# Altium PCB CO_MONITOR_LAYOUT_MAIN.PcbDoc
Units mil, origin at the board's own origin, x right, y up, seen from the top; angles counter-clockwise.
Board outline 2980 x 4230 mil, 2 copper layers (Top Layer, Bottom Layer); 116 components, 104 nets, 435 pads, 124 vias.
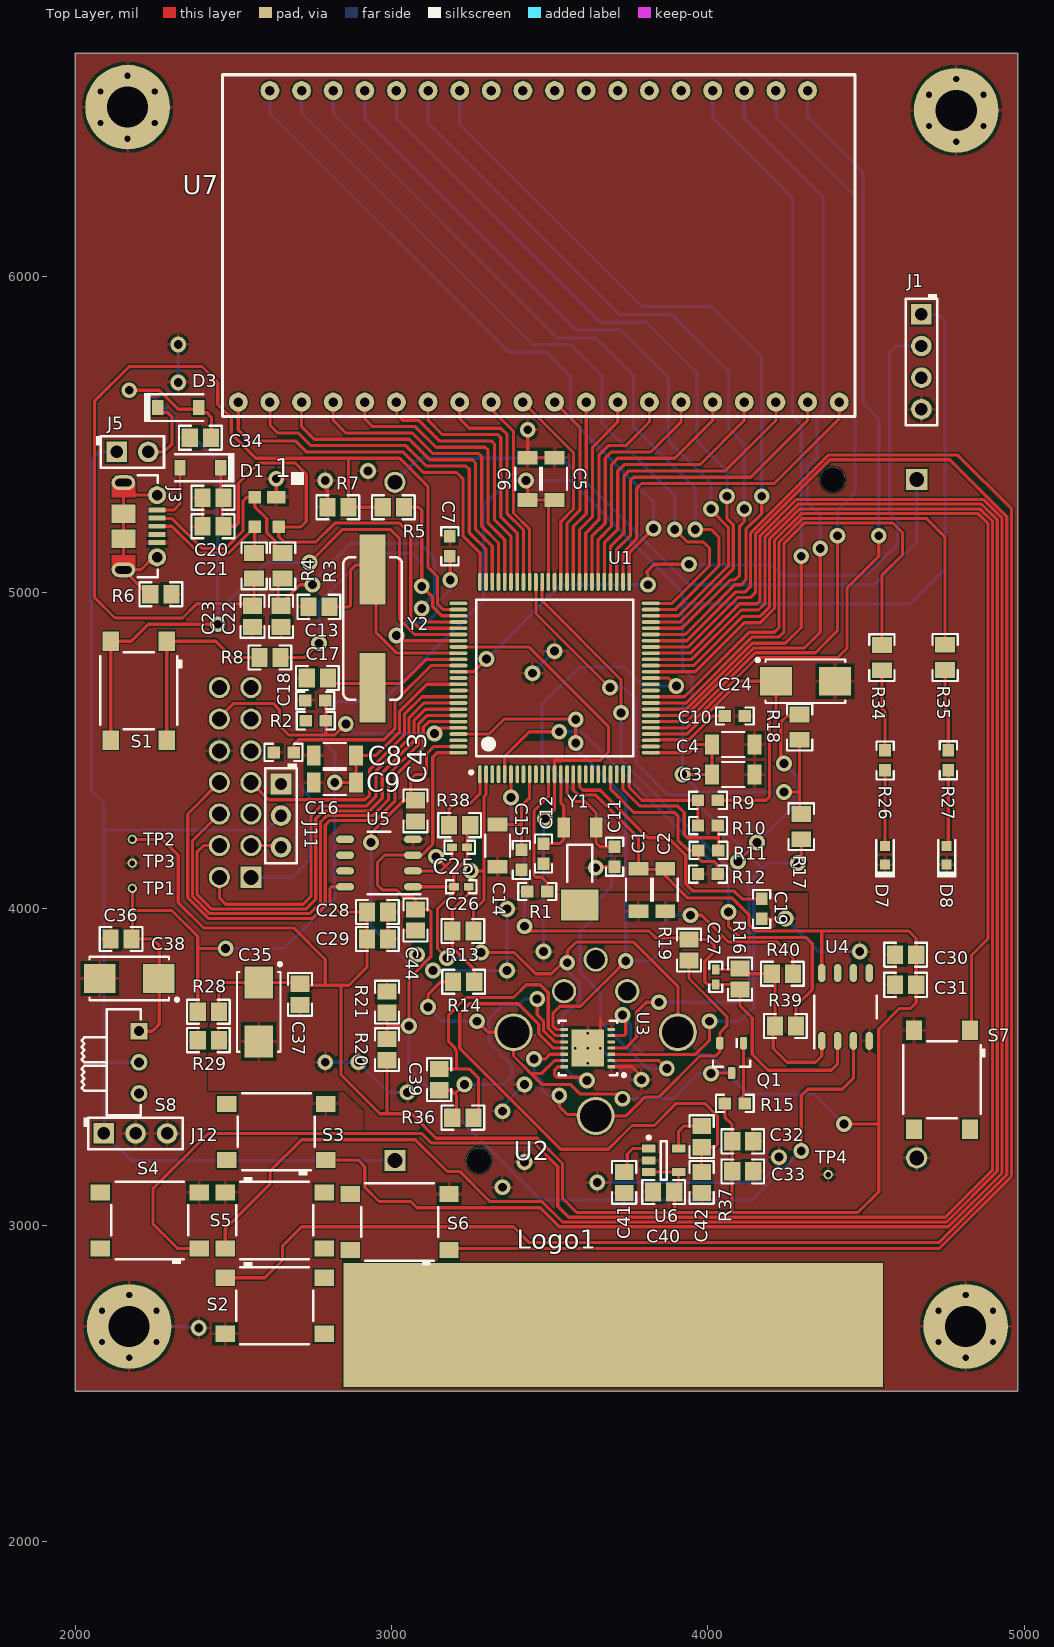
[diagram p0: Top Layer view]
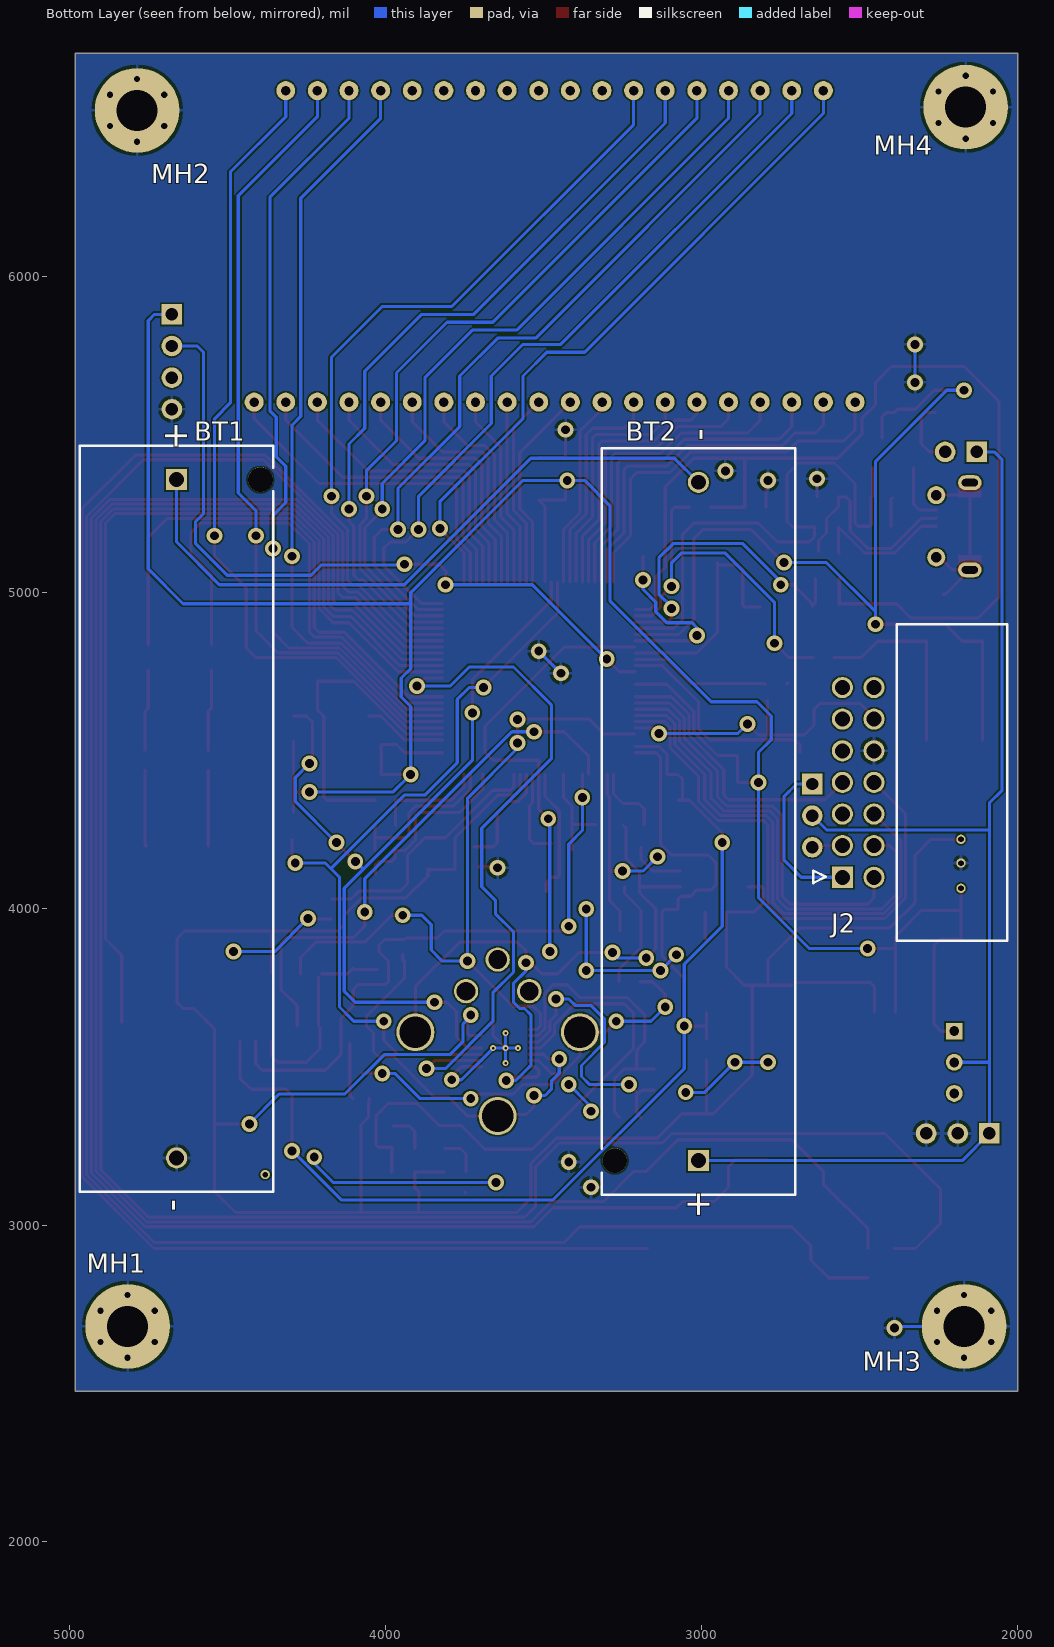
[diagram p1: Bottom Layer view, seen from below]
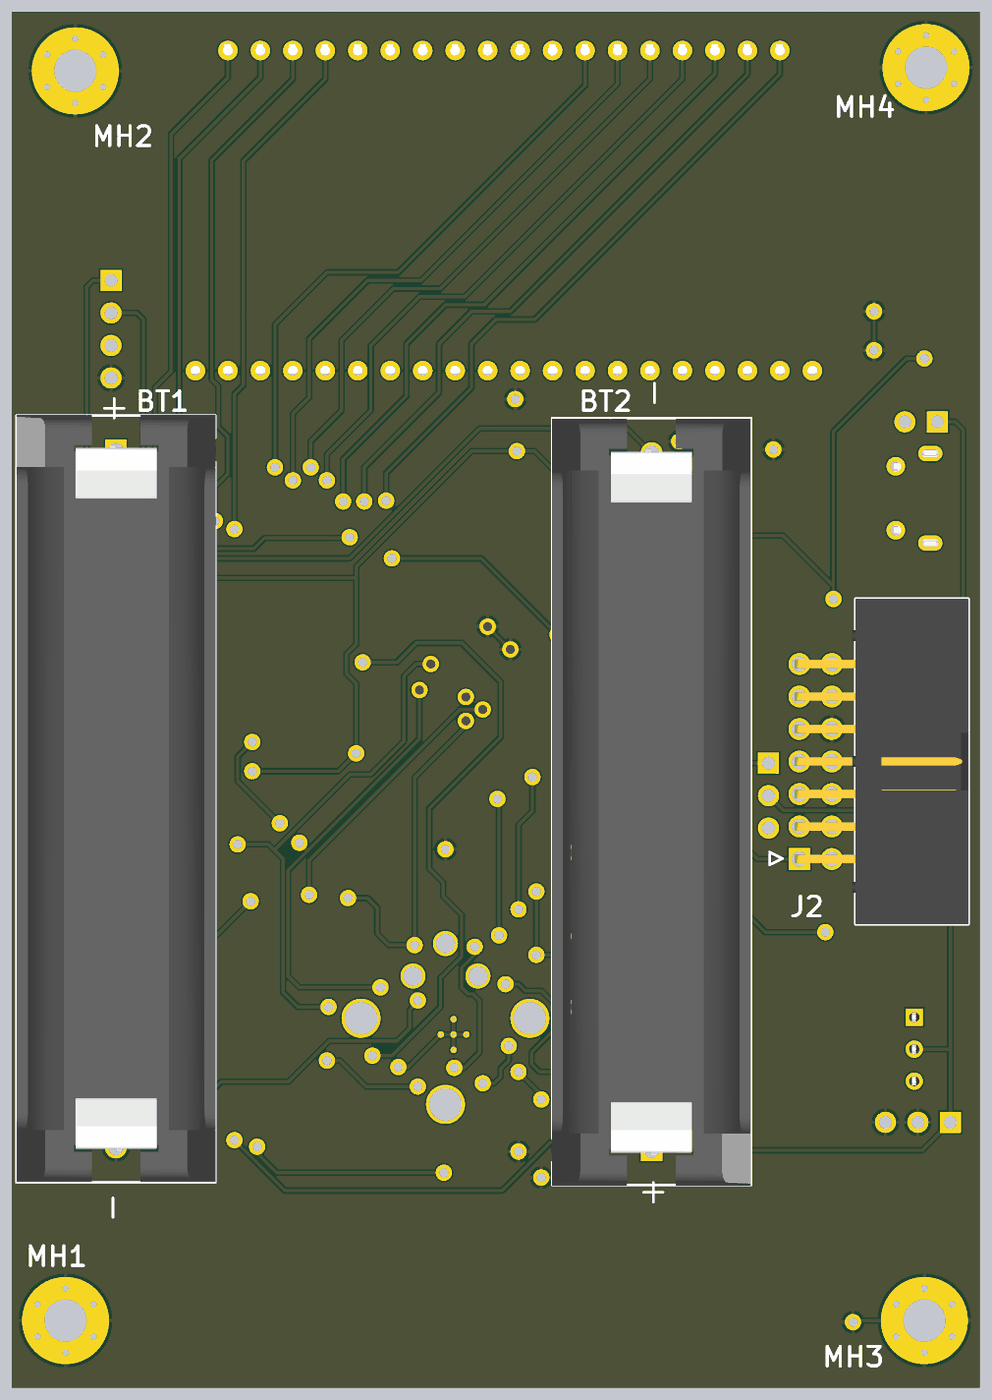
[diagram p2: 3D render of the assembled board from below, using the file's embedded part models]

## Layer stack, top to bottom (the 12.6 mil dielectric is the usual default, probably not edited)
Top Solder: solder mask 0.4, Solder Resist, Dk 3.5
Top Layer: signal copper 1.4
Dielectric 1: dielectric 12.6, FR-4, Dk 4.8
Bottom Layer: signal copper 1.4
Bottom Solder: solder mask 0.4, Solder Resist, Dk 3.5

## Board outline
2000,6705 4980,6705 4980,6680 4980,2475 4365,2475 2000,2475 2000,2480 2000,6705

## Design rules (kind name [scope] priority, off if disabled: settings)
Clearance Clearance_Power_Polugone [(InPolygon AND InNetClass('All Nets'))] p1: gap=5
Clearance [All] p2: gap=4
ComponentClearance [All] p1: gap=9 collisioncheckmode=3 verticalgap=0 showdistances=FALSE
HoleSize [All] p1: absolutevalues=TRUE maxlimit=240 minlimit=5 maxpercent=80.000 minpercent=20.000
MinimumAnnularRing [All] p1: minimumring=5
MinimumSolderMaskSliver [All] p1: minsoldermaskwidth=2
PlaneConnect [All] p1: planeconnectstyle=Relief reliefexpansion=20 reliefentries=4 reliefconductorwidth=10 reliefairgap=50
PolygonConnect [All] p1: connectstyle=Relief reliefconductorwidth=10 reliefentries=4 polygonreliefangle="90 Angle" airgapwidth=10
RoutingVias [All] p1: holewidth=28 width=50 viastyle="Through Hole" minholewidth=28 minwidth=50 maxholewidth=28 maxwidth=50
SilkToSilkClearance [All] p1: silktosilkclearance=5
SilkToSolderMaskClearance [IsPad] p1: minsilkscreentomaskgap=5 clearancetoexposedcopper=TRUE
SolderMaskExpansion [All] p1: expansion=0
Width [All] p1: maxlimit=10 minlimit=10 preferedwidth=10
24 further rules are at their usual default settings.

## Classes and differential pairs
component class CO_MONITOR_3_USB_SUBCIRCUIT: 1 C20 C21 C22 C23 D1 J3 R3 R4 R5 R6 R7 R8 S1
component class CO_MONITOR_2_JTAG_SBW: J2
component class CO_MONITOR_4_LCD: C24 R9 R10 R11 R12 S2 S3 S4 S5 S6 S7 U7
component class CO_MONITOR_5_GASDETECTION_SUBCIRCUIT: C25 C26 C27 C28 C29 C30 C31 C32 C33 C39 C40 C41 C42 C43 C44 Q1 R13 R14 R15 R16 R17 R18 R19 R36 R37 R38 R39 R40 U2 U3 U4 U5 U6
component class CO_MONITOR_6_POWER_SUPPLY: BT1 BT2 C35 C36 C37 C38 J11 J12 R20 R21 R28 R29 S8 TP1 TP2 TP3 TP4 TP5
component class CO_MONITOR_7_MISCELLANEOUS: C34 D3 D7 D8 J5 Logo1 MH1 MH2 MH3 MH4 R26 R27 R34 R35
component class CO_MONITOR_1_MSP430FG6626: C1 C2 C3 C4 C5 C6 C7 C8 C9 C10 C11 C12 C13 C14 C15 C16 C17 C18 C19 J1 R1 R2 U1 Y1 Y2
component class Header: J1 J5 J11 J12
component class Logo: Logo1

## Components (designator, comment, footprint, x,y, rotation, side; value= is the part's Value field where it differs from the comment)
1 "TPD2E001DZDR" DZD 2605,5255 r180 top
BT1 "1015" Keystone_1015 4660,4285 r270 bottom
BT2 "1015" Keystone_1015 3010,4276.54 r90 bottom
C1 "C3216NP01H104J160AA" 1206_190 3780,4060 r270 top
C2 "C3216NP01H104J160AA" 1206_190 3865,4060 r270 top
C3 "C3216NP01H104J160AA" 1206_190 4080,4425 r0 top
C4 "C3216NP01H104J160AA" 1206_190 4080,4520 r0 top
C5 "C3216NP01H104J160AA" 1206_190 3515,5360 r90 top
C6 "C3216NP01H104J160AA" 1206_190 3430,5360 r90 top
C7 "C1608X7R1H224K080AB" 0603 3183.83,5146.94 r90 top
C8 "C3216NP01H104J160AA" 1206_190 2820,4485 r180 top
C9 "C3216NP01H104J160AA" 1206_190 2820,4400 r180 top
C10 "GRM188R61C474KA93D" 0603 4085,4610 r0 top
C11 "C1608C0G1H120J" 0603 3705,4165 r90 top
C12 "C1608C0G1H120J" 0603 3480,4175 r90 top
C13 "C0805C180J5GACTU" 0805 2770,4955 r180 top
C14 "C3216NP01H104J160AA" 1206_190 3335,4200 r270 top
C15 "GRM188R60J106ME84" 0603 3410,4155 r270 top
C16 "C0603C472J5RACTU" 0603 2658.19,4495 r0 top
C17 "C0805C180J5GACTU" 0805 2765,4730 r180 top
C18 "GRM188R71C222KA01D" 0603 2758.19,4658.83 r180 top
C19 "GRM188R71H223KA01D" 0603 4170,4000 r90 top
C20 "GRM21BC81E475KA12L" 0805 2435,5300 r180 top
C21 "GRM21BR71H104KA01L" 0805 2435,5210 r180 top
C22 "08055A100JAT2A" 0805 2650,4925 r270 top
C23 "08055A100JAT2A" 0805 2560,4925 r270 top
C24 "293D475X9025C2TE3" 6032-28 4308.31,4720 r0 top
C25 "500R07S0R3BV4T" 0402 3215,4195 r0 top
C26 "500R07S0R3BV4T" 0402 3220,4070 r180 top
C27 "500R07S0R3BV4T" 0402 4024.84,3785 r90 top
C28 "08055C104JAT2A" 0805 2955,3990 r0 top
C29 "08055C104JAT2A" 0805 2955,3905 r0 top
C30 "08055C104JAT2A" 0805 4625,3855 r180 top
C31 "08055C104JAT2A" 0805 4625,3760 r180 top
C32 "08055C104JAT2A" 0805 4110,3265 r0 top
C33 "08055C104JAT2A" 0805 4110,3170 r0 top
C34 "GRM219R71E224KA01D" 0805 2395,5490 r180 top
C35 "293D106X9020C2TE3" 6032-28 2579.65,3674.18 r270 top
C36 "C0805C104K4RACTU" 0805 2144.18,3904.68 r180 top
C37 "C0805C104K4RACTU" 0805 2710,3730 r270 top
C38 "293D106X9020C2TE3" 6032-28 2170,3780 r180 top
C39 "C0805C105K4RACTU" 0805 3150,3460 r90 top
C40 "08055C104JAT2A" 0805 3860,3105 r180 top
C41 "08055A560JAT2A" 0805 3735,3135 r270 top
C42 "08055C223KAT2A" 0805 3980,3135 r270 top
C43 "08055C104JAT2A" 0805 3075,4310 r270 top
C44 "08055C104JAT2A" 0805 3075,3965 r270 top
D1 "SD103AW-7-F" SOD-123 2395,5395 r180 top
D3 "SD103AW-7-F" SOD-123 2325,5585 r0 top
D7 "19-21SURC/S530-A3/TR8" 19-21_Red 4560,4169.53 r90 top
D8 "19-21SURC/S530-A3/TR8" 19-21_Red 4755,4170 r90 top
J1 "5-146278-4" TE_5-146278-4 4675,5730 r270 top
J2 "612 014 217 21" WURTH_612_014_217_21 2505,4400 r90 bottom
J3 "105017-0001" CONN_105017-0001 2205,5210 r270 top
J5 "5-146278-2" TE_5-146278-2 2180,5445 r0 top
J11 "5-146278-3" TE_5-146278-3 2650,4295 r270 top
J12 "5-146278-3" TE_5-146278-3 2190,3290 r0 top
Logo1 "Texas Instruments" TI_Stacked_SolderMask_Medium 3700,2685 r0 top
MH1 "MTG_Pads" MTGP_M3_PanHead 4815,2680 r0 bottom
MH2 "MTG_Pads" MTGP_M3_PanHead 4785,6525 r0 bottom
MH3 "MTG_Pads" MTGP_M3_PanHead 2170,2680 r0 bottom
MH4 "MTG_Pads" MTGP_M3_PanHead 2165,6535 r0 bottom
Q1 "BSH201,215" SOT-23 4075,3528.46 r270 top
R1 "CRCW06030000Z0EA" 0603 3460,4055 r0 top
R2 "RT0603BRD0747KL" 0603 2760,4595 r180 top
R3 "CRCW080527R0JNEA" 0805_HV 2655,5085 r270 top
R4 "CRCW080527R0JNEA" 0805_HV 2565,5085 r270 top
R5 "CRCW08051K40FKEA" 0805 3005,5270 r0 top
R6 "CRCW080533K0JNEA" 0805 2270,4995 r180 top
R7 "CRCW08051M00JNEA" 0805 2830,5270 r0 top
R8 "RT0805BRD07100RL" 0805 2615,4795 r180 top
R9 "CRCW06030000Z0EA" 0603 4000,4343.5 r0 top
R10 "CRCW06030000Z0EA" 0603 4000,4263.5 r180 top
R11 "CRCW06030000Z0EA" 0603 4001.5,4185 r0 top
R12 "CRCW06030000Z0EA" 0603 4000,4110 r0 top
R13 "RG2012P-103-B-T5" 0805 3225,3930 r0 top
R14 "RG2012P-103-B-T5" 0805 3227.75,3769.65 r0 top
R15 "CRCW060310K0FKEA" 0603 4085,3385 r180 top
R16 "RG2012P-103-B-T5" 0805 4101.5,3778.5 r270 top
R17 "RG2012P-332-B-T5" 0805_HV 4295,4260 r270 top
R18 "RG2012P-332-B-T5" 0805_HV 4290,4575 r90 top
R19 "ERJ-6GEYJ102V" 0805 3940,3870 r90 top
R20 "RG2012P-103-B-T5" 0805 2985,3555 r270 top
R21 "RG2012P-103-B-T5" 0805 2985,3705 r270 top
R26 "CRCW0603470RJNEA" 0603 4560,4469.53 r270 top
R27 "CRCW0603470RJNEA" 0603 4760,4470 r270 top
R28 "CRCW08050000Z0EA" 0805 2420,3675 r0 top
R29 "CRCW08050000Z0EA" 0805 2420,3585 r0 top
R34 "MCR10EZPJ000" 0805_HV 4550,4794.53 r270 top
R35 "MCR10EZPJ000" 0805_HV 4750,4795 r270 top
R36 "CRCW08051K10JNEA" 0805 3225,3340 r180 top
R37 "CRCW08050000Z0EA" 0805 3980,3280 r270 top
R38 "CRCW08050000Z0EA" 0805 3215,4265 r0 top
R39 "CRCW08050000Z0EA" 0805 4245,3630 r0 top
R40 "CRCW08050000Z0EA" 0805 4235,3795 r0 top
S1 "430182080816" SW_430182080816 2200,4690 r270 top
S2 "430182080816" SW_430182080816 2630,2745 r0 top
S3 "430182080816" SW_430182080816 2635,3295 r180 top
S4 "430182080816" SW_430182080816 2235,3015 r180 top
S5 "430182080816" SW_430182080816 2630,3015 r0 top
S6 "430182080816" SW_430182080816 3025,3010 r180 top
S7 "430182080816" SW_430182080816 4740,3460 r270 top
S8 "MHSS1105" SW_MHSS1105 2150,3515 r270 top
TP1 "TESTPOINT" TP_H045P075 2180,4065 r270 top
TP2 "TESTPOINT" TP_H045P075 2180,4220 r90 top
TP3 "TESTPOINT" TP_H045P075 2180,4145 r270 top
TP4 "TESTPOINT" TP_H045P075 4380,3160 r90 top
U1 "MSP430FG6626IPZR" PZ0100A_N 3515,4730 r90 top
U2 "CO_AF" CO_AF 3645,3610 r180 top
U3 "LMP91000_NHL_14" SDA14B 3620,3560 r180 top
U4 "LMC6442AIM" D0008A_N 4435,3690 r90 top
U5 "LMC6442AIM" D0008A_N 2960,4145 r180 top
U6 "LM4120AIM5-2.5/NOPB" MF05A_N 3860,3205 r0 top
U7 "FH1138P" FH1138P 3465,6095 r0 top
Y1 "MS1V-T1K 32.768KHZ +-20PPM 12.5PF" XTAL_MS1V-T1K 3595,4135 r270 top
Y2 "ABLS2-4.000MHZ-D4Y-T" ABRACON_ABLS2 2939.8,4886.54 r90 top

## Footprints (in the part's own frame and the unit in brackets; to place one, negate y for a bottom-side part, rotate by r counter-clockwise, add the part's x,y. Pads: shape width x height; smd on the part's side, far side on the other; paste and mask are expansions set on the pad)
19-21_Red [mm] "SMD, 2-Leads, Body 0.8x1.6mm, Pin Spacing 1.5mm"
  rect 0.8x0.8 smd: 1(-0.75,0) 2(0.75,0)
  silkscreen extent -1.8,-0.8 1.2,0.8, body extent -0.9,-0.45 0.9,0.45, height 1.01
0402 [mm] "0402 from SM-752 data"
  rect 0.8x0.6 smd: 1(-0.6,0) 2(0.6,0)
  silkscreen extent -1.22,-0.52 1.22,0.52, body extent -0.55,-0.3 0.55,0.3, height 0.6
0603 [mm] "0603 from SM-752 data"
  rect 1x0.95 smd: 1(-0.8,0) 2(0.8,0)
  silkscreen extent -1.52,-0.69 1.52,0.69, body extent -0.87,-0.47 0.87,0.47, height 0.85
0805 [mm] "0805 from SM-752 data"
  rect 1.3x1.5 smd: 1(-0.85,0) 2(0.85,0)
  silkscreen extent -1.72,-0.97 1.72,0.97, body extent -1.1,-0.72 1.1,0.72, height 1.45
0805_HV [mil] "0805 with 30mil clearance between pads"
  rect 50x63 smd: 1(-40,0) 2(40,0)
  silkscreen extent -74,-40 74,40, body extent -43,-29 43,29, height 57
1206_190 [mm] "1206_190"
  rect 1.1x1.6 smd: 1(-1.7,0) 2(1.7,0)
  silkscreen extent -0.9,-1 0.9,1, body extent -1.75,-0.95 1.75,0.95, height 1.9
6032-28 [mm] "Medium Density IPC based on Vishay Sprague 293D datasheet."
  rect 2.55x2.3 smd: 1(-2.375,0) 2(2.375,0)
  silkscreen extent -3.96,-1.75 3.2,1.82, body extent -3.15,-1.75 3.15,1.75, height 2.8
ABRACON_ABLS2 [mm] "SMD, 2-Leads, Body 11.4x4.7mm"
  rect 5.6x2.1 smd: 1(-4.75,0) 2(4.75,0)
  silkscreen extent -5.71,-2.35 5.72,2.35, body extent -6.35,-2.35 6.35,2.35, height 3.27
CO_AF [mil]
  round 120 hole 100: 1(-260,0) 2(260,0) 3(0,265)
  round 76.93 hole 59.06: 7(0,-230) 8(100,-130) 9(-100,-130)
  body extent -347,-324 359,384, height 690
CONN_105017-0001 [mm] "Molex Micro USB-B"
  rect 0.4x1.35 smd mask+0.051: 1(-1.3,1.35) 2(-0.65,1.35) 3(0,1.35) 4(0.65,1.35) 5(1.3,1.35)
  oval 1.2x1.9 hole 0.6 slot 1.3 at 90 deg: 6(-3.5,-1.35) 9(3.5,-1.35)
  rect 1.5x1.9 smd: 7(-1,-1.35) 8(1,-1.35)
  round 1.45 hole 0.85: 10(2.5,1.35) 11(-2.5,1.35)
  Top Layer region: 3.5,-0.4 2.3,-0.4 2.3,-2.3 3.5,-2.3
  Top Layer region: -3.5,-2.3 -2.3,-2.3 -2.3,-0.4 -3.5,-0.4
  silkscreen extent -4.1,-0.2 4.1,1.4, body extent -4.1,-3.93 4.1,1.5, height 2.72
D0008A_N [mm] "SOIC, 8-Leads, Body 4.9x3.9mm, Pitch 1.27mm, IPC Medium Density"
  oval 1.45x0.6 smd: 1(-2.725,1.905) 2(-2.725,0.635) 3(-2.725,-0.635) 4(-2.725,-1.905) 5(2.725,-1.905) 6(2.725,-0.635) 7(2.725,0.635) 8(2.725,1.905)
  silkscreen extent -3.3,-2.5 0.9,2.5, body extent -3,-2.45 3,2.45, height 1.63
DZD [mm]
  rect 1.5x1 smd: 1(-0.76,-1.2)
  rect 1x1 smd mask+0.05: 2(0.96,-1.2) 3(0.96,1.2) 4(-0.96,1.2)
  silkscreen extent -2.99,-3.21 -1.97,-2.19
FH1138P [mil]
  round 60 hole 30: 1(-950,-492.5) 2(-850,-492.5) 3(-750,-492.5) 4(-650,-492.5) 5(-550,-492.5) 6(-450,-492.5) 7(-350,-492.5) 8(-250,-492.5) 9(-150,-492.5) 10(-50,-492.5) 11(50,-492.5) 12(150,-492.5) 13(250,-492.5) 14(350,-492.5) 15(450,-492.5) 16(550,-492.5) 17(650,-492.5) 18(750,-492.5) 19(850,-492.5) 20(950,-492.5) 21(850,492.5) 22(750,492.5) 23(650,492.5) 24(550,492.5) 25(450,492.5) 26(350,492.5) 27(250,492.5) 28(150,492.5) 29(50,492.5) 30(-50,492.5) 31(-150,492.5) 32(-250,492.5) 33(-350,492.5) 34(-450,492.5) 35(-550,492.5) 36(-650,492.5) 37(-750,492.5) 38(-850,492.5)
  silkscreen extent -1000,-538 1000,542, body extent -1080,-501 1085,511, height 202
Keystone_1015 [mm] "AA Battery Holder, Through-hole mount"
  rect 1.7x1.7 hole 1.19: 1(-27.24,0)
  round 1.7 hole 1.19: 2(27.24,0)
  round 1.98 hole 1.98 unplated paste+0 mask+0: MH1(-27.24,6.73)
  silkscreen extent -29.97,-7.77 29.97,7.77, body extent -30,-7.74 29.93,7.8, height 14.86
MF05A_N [mm] "SOT23, 5-Leads, Body 2.9x1.6mm, Pitch 0.95mm, Lead Span 2.8mm, IPC Medium Density"
  rect 1.1x0.65 smd: 1(-1.2,0.95) 2(-1.2,0) 3(-1.2,-0.95) 4(1.2,-0.95) 5(1.2,0.95)
  silkscreen extent -1.32,-1.55 0.25,1.95, body extent -0.9,-1.55 0.9,1.55, height 1.19
MTGP_M3_PanHead [mm] "M3Mounting Hole, Plated, for Pan Head"
  round 6.8 hole 3.3: 1(0,0)
PZ0100A_N [mm] "TSQFP, 100-Leads, Body 16.2x16.2mm (max), Pitch 0.50mm, IPC Medium Density"
  oval 1.45x0.3 smd: 1(-7.725,6) 2(-7.725,5.5) 3(-7.725,5) 4(-7.725,4.5) 5(-7.725,4) 6(-7.725,3.5) 7(-7.725,3) 8(-7.725,2.5) 9(-7.725,2) 10(-7.725,1.5) 11(-7.725,1) 12(-7.725,0.5) 13(-7.725,0) 14(-7.725,-0.5) 15(-7.725,-1) 16(-7.725,-1.5) 17(-7.725,-2) 18(-7.725,-2.5) 19(-7.725,-3) 20(-7.725,-3.5) 21(-7.725,-4) 22(-7.725,-4.5) 23(-7.725,-5) 24(-7.725,-5.5) 25(-7.725,-6) 51(7.725,-6) 52(7.725,-5.5) 53(7.725,-5) 54(7.725,-4.5) 55(7.725,-4) 56(7.725,-3.5) 57(7.725,-3) 58(7.725,-2.5) 59(7.725,-2) 60(7.725,-1.5) 61(7.725,-1) 62(7.725,-0.5) 63(7.725,0) 64(7.725,0.5) 65(7.725,1) 66(7.725,1.5) 67(7.725,2) 68(7.725,2.5) 69(7.725,3) 70(7.725,3.5) 71(7.725,4) 72(7.725,4.5) 73(7.725,5) 74(7.725,5.5) 75(7.725,6)
  oval 0.3x1.45 smd: 26(-6,-7.725) 27(-5.5,-7.725) 28(-5,-7.725) 29(-4.5,-7.725) 30(-4,-7.725) 31(-3.5,-7.725) 32(-3,-7.725) 33(-2.5,-7.725) 34(-2,-7.725) 35(-1.5,-7.725) 36(-1,-7.725) 37(-0.5,-7.725) 38(0,-7.725) 39(0.5,-7.725) 40(1,-7.725) 41(1.5,-7.725) 42(2,-7.725) 43(2.5,-7.725) 44(3,-7.725) 45(3.5,-7.725) 46(4,-7.725) 47(4.5,-7.725) 48(5,-7.725) 49(5.5,-7.725) 50(6,-7.725) 76(6,7.725) 77(5.5,7.725) 78(5,7.725) 79(4.5,7.725) 80(4,7.725) 81(3.5,7.725) 82(3,7.725) 83(2.5,7.725) 84(2,7.725) 85(1.5,7.725) 86(1,7.725) 87(0.5,7.725) 88(0,7.725) 89(-0.5,7.725) 90(-1,7.725) 91(-1.5,7.725) 92(-2,7.725) 93(-2.5,7.725) 94(-3,7.725) 95(-3.5,7.725) 96(-4,7.725) 97(-4.5,7.725) 98(-5,7.725) 99(-5.5,7.725) 100(-6,7.725)
  silkscreen extent -7.7,-6.3 6.3,6.82, body extent -8.01,-8.01 8.01,8.01, height 1.6
SDA14B [mm] "SON, 14-Leads, Body 4x4mm, Pitch 0.5mm, NSC Recommended"
  rect 0.6x0.25 smd paste-0.125 mask+0.051: 1(-1.9,1.5) 2(-1.9,1) 3(-1.9,0.5) 4(-1.9,0) 5(-1.9,-0.5) 6(-1.9,-1) 7(-1.9,-1.5) 8(1.9,-1.5) 9(1.9,-1) 10(1.9,-0.5) 11(1.9,0) 12(1.9,0.5) 13(1.9,1) 14(1.9,1.5)
  rect 2.6x3 smd paste-1.3 mask+0.051: 15(0,0)
  silkscreen extent -3.03,-2.2 2.35,2.3, body extent -2.05,-2.05 2.05,2.05, height 0.8
SOD-123 [mm] "On Semi recommended land pattern"
  rect 0.915x1.22 smd: 1(-1.637,0) 2(1.637,0)
  silkscreen extent -2.74,-1.17 2.03,1.17, body extent -1.93,-0.9 1.93,0.9, height 1.35
SOT-23 [mm] "SOT23, 3-Leads, Body 2.9x1.3mm, Pitch 0.95mm, Lead Span 2.5mm, IPC Medium Density"
  rrect50% 1x0.6 smd: 1(-1.2,0.95) 2(-1.2,-0.95) 3(1.2,0)
  silkscreen extent -1.63,-1.5 0.7,1.5, body extent -1.16,-1.45 1.21,1.45, height 1
SW_430182080816 [mm] "SMD, 4-Leads, Body 6.2x6.2mm"
  rect 1.55x1.3 smd: 1(-3.975,2.25) 2(-3.975,-2.25) 3(3.975,2.25) 4(3.975,-2.25)
  silkscreen extent -3.1,-3.1 3.1,3.5, body extent -4.5,-3.1 4.5,3.1, height 8
SW_MHSS1105 [mm] "APEM"
  rect 1.35x1.35 hole 0.8: 1(-2.5,1.3)
  round 1.35 hole 0.8: 2(0,1.3) 3(2.5,1.3)
  silkscreen extent -4.25,-3.31 4.26,1.45, body extent -4.25,-3.3 4.25,2.21, height 5.06
TE_5-146278-2 [mm] "TE CONNECTIVITY"
  rect 1.65x1.65 hole 1: 1(-1.27,0)
  round 1.65 hole 1: 2(1.27,0)
  silkscreen extent -2.92,-1.27 2.54,1.27, body extent -2.41,-1.17 2.41,1.17, height 8.13
TE_5-146278-3 [mm] "TE CONNECTIVITY"
  rect 1.65x1.65 hole 1: 1(-2.54,0)
  round 1.65 hole 1: 2(0,0) 3(2.54,0)
  silkscreen extent -4.19,-1.27 3.81,1.27, body extent -3.68,-1.17 3.68,1.17, height 8.13
TE_5-146278-4 [mm] "TE CONNECTIVITY"
  rect 1.65x1.65 hole 1: 1(-3.81,0)
  round 1.65 hole 1: 2(-1.27,0) 3(1.27,0) 4(3.81,0)
  silkscreen extent -5.46,-1.27 5.08,1.27, body extent -4.95,-1.17 4.95,1.17, height 8.13
TI_Stacked_SolderMask_Medium [mil]
  rect 1706x392 smd paste-196 mask-196: 0(0,0)
TP_H045P075 [mm] "TP_H0.45P0.75"
  round 0.75 hole 0.45: 1(0,0)
WURTH_612_014_217_21 [mm] "Header, 2.54 mm, 7x2, R/A, TH"
  rect 1.7x1.7 hole 1.2: 1(-7.62,1.27)
  round 1.7 hole 1.2: 2(-7.62,-1.27) 3(-5.08,1.27) 4(-5.08,-1.27) 5(-2.54,1.27) 6(-2.54,-1.27) 7(0,1.27) 8(0,-1.27) 9(2.54,1.27) 10(2.54,-1.27) 11(5.08,1.27) 12(5.08,-1.27) 13(7.62,1.27) 14(7.62,-1.27)
  silkscreen extent -12.72,-11.96 12.72,3.6, body extent -12.72,-11.96 12.72,1.59, height 9.1
XTAL_MS1V-T1K [mm] "SMD, 3-Leads, Body 2.0x8.1x2.0mm"
  rect 1.6x1 smd: 1(-3.125,1.3) 2(-3.125,-1.3)
  rect 2.5x3 smd: 3(3.125,0)
  silkscreen extent -1.73,-1 1.25,1, body extent -3.72,-1.38 4.38,1.38, height 2.08

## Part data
1: "IC, Low-Capacitacnce 2-Chan ±15-kV ESD-Protection Array"
BT1 BT2: "AA Battery Holder, Through-hole mount"
C1 C2 C3 C4 C5 C6 C8 C9 C14: "CAP, CERM, 0.1 µF, 50 V, +/- 5%, C0G/NP0, 1206_190"
C7: "CAP, CERM, 0.22 µF, 50 V, +/- 10%, X7R, 0603"
C10: "CAP, CERM, 0.47 µF, 16 V, +/- 10%, X5R, 0603"
C11 C12: "CAP, CERM, 12 pF, 50 V, +/- 5%, C0G/NP0, 0603"
C13 C17: "CAP, CERM, 18 pF, 50 V, +/- 5%, C0G/NP0, 0805"
C15: "CAP, CERM, 10 µF, 6.3 V, +/- 20%, X5R, 0603"
C16: "CAP, CERM, 4700 pF, 50 V, +/- 5%, X7R, 0603"
C18: "CAP, CERM, 2200 pF, 16 V, +/- 10%, X7R, 0603"
C19: "CAP, CERM, 0.022 µF, 50 V, +/- 10%, X7R, 0603"
C20: "CAP, CERM, 4.7 µF, 25 V, +/- 10%, X6S, 0805"
C21: "CAP, CERM, 0.1 µF, 50 V, +/- 10%, X7R, 0805"
C22 C23: "CAP, CERM, 10 pF, 50 V, +/- 5%, C0G/NP0, 0805"
C24: "CAP, TA, 4.7 µF, 25 V, +/- 10%, 2 ohm, SMD"
C25 C26 C27: "CAP, CERM, 0.3 pF, 50 V, +/- 30%, C0G/NP0, 0402"
C28 C29 C30 C31 C32 C33 C40 C43 C44: "CAP, CERM, 0.1 µF, 50 V, +/- 5%, X7R, 0805"
C34: "CAP, CERM, 0.22 µF, 25 V, +/- 10%, X7R, 0805"
C35 C38: "CAP, TA, 10 µF, 20 V, +/- 10%, 1.7 ohm, SMD"
C36 C37: "CAP, CERM, 0.1 µF, 16 V, +/- 10%, X7R, 0805"
C39: "CAP, CERM, 1 µF, 16 V, +/- 10%, X7R, 0805"
C41: "CAP, CERM, 56 pF, 50 V, +/- 5%, C0G/NP0, 0805"
C42: "CAP, CERM, 0.022 µF, 50 V, +/- 10%, X7R, 0805"
D1 D3: "Diode, Schottky, 40 V, 0.35 A, SOD-123"
D7 D8: "LED, Red, SMD"
J1: "Header, 100mil, 4x1, Tin, TH"
J2: "Header (Shrouded), 2.54 mm, 7x2, Gold, R/A, TH"
J3: "Connector, Receptacle, Micro-USB Type B, R/A, Bottom Mount SMT"
J5: "Header, 100mil, 2x1, Tin, TH"
J11 J12: "Header, 100mil, 3x1, Tin, TH"
Logo1: library part TI_Logo, "Texas Instrument Corporate Signature"
MH1 MH2 MH3 MH4: library part "Mounting Hole (Metric) with Pads", "PCB Mounting Hole"
Q1: "MOSFET, P-CH, -60 V, -0.3 A, SOT-23"
R1 R9 R10 R11 R12: "RES, 0, 5%, 0.1 W, 0603"
R2: "RES, 47.0 k, 0.1%, 0.1 W, 0603"
R3 R4: "RES, 27, 5%, 0.125 W, 0805"
R5: "RES, 1.40 k, 1%, 0.125 W, 0805"
R6: "RES, 33 k, 5%, 0.125 W, 0805"
R7: "RES, 1.0 M, 5%, 0.125 W, 0805"
R8: "RES, 100, 0.1%, 0.125 W, 0805"
R13 R14 R16 R20 R21: "RES, 10.0 k, 0.1%, 0.125 W, 0805"
R15: "RES, 10.0 k, 1%, 0.1 W, 0603"
R17 R18: "RES, 3.30 k, 0.1%, 0.125 W, 0805"
R19: "RES, 1.0 k, 5%, 0.125 W, 0805"
R26 R27: "RES, 470, 5%, 0.1 W, 0603"
R28 R29 R34 R35 R37 R38 R39 R40: "RES, 0, 5%, 0.125 W, 0805"
R36: "RES, 1.1 k, 5%, 0.125 W, 0805"
S1 S2 S3 S4 S5 S6 S7: "Switch, Tactile, SPST-NO, 0.05A, 12V, SMD"
S8: "Switch, Slide, SPDT, R/A, TH"
TP1 TP2 TP3 TP4: library part TP_H0.45P0.75, "Testpoint"
U1: "Mixed-Signal Microcontrollers, PZ0100A"
U3: "Imported"
U4 U5: "Dual Micropower Rail-to-Rail Output Operational Amplifier, D0008A"
U6: "Precision Micropower Low Dropout Voltage Reference, 5-pin SOT-23, Pb-Free"
Y1: "Tuning Fork Crystal, 32.768 kHz, 12.5 pF, SMD"
Y2: "Crystal, 4MHz, 18pF, SMD"

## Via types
v1: diameter 50, hole 28, Top Layer to Bottom Layer, 66 vias
v2: diameter 50, hole 28, Top Layer to Bottom Layer, tented top, 29 vias
v3: diameter 39.37, hole 19.68, Top Layer to Bottom Layer, 24 vias
v4: diameter 19.68, hole 7.87, Top Layer to Bottom Layer, tented top, 5 vias

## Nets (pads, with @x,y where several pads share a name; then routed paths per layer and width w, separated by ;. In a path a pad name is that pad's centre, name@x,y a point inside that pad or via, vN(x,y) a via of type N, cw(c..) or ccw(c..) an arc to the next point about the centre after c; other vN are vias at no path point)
AVCC: C1.1 C2.1 C28.1 C29.1 C30.1 C31.1 C32.1 C33.1 C35.1 C37.1 C40.1 R15.2 R20.2 R28.2 TP2.1 U1.16 U3.6 U4.8 U5.8 U6.3 U6.4 | length 8473.3
  Top Layer w10: TP2.1 2275,4220 2325,4170 2325,4020 2405,3940 2690,3940 2790,3840 2790,3758.46 ; R28.2 2453.46,3753.46 2467.68,3767.68 C35.1 C37.1@2705.78,3767.68 ; C37.1@2715,3758.46 2790,3758.46 ; U5.8 2810,4070 2805,4065 2805,4020 2835,3990 C28.1 C29.1 2921.54,3815 2865,3758.46 2840,3758.46 ; R20.2 2985,3352.13 ; U1.16 3574.06,4375.94 3590,4360 3645,4360 3780,4225 3780,4125 3855,4125 C2.1@3870,4110 ; U3.6 3734.37,3599.37 3740,3605 3740,3650 3725,3665 v2(3730,3665) ; U6.3 U6.4 3907.24,3118.78 C40.1 3895,3040 ; C2.1 3865,4105 3935,4035 4075,4035 4130,3980 4130,3950 4150,3930 4360,3930 ; R15.2@4051.54,3385 R15.2@4051.54,3401.97 ; R15.2 4053.5,3341.5 4076.54,3318.46 C32.1 C33.1 4076.54,3041.54 4075,3040 ; U4.8 4360,3930 ; v1(4430,3320) 4540,3320 ; 2790,3758.46 2840,3758.46 ; 2840,3758.46 2840,3475 2962.87,3352.13 2985,3352.13 ; 2985,3352.13 3062.87,3352.13 3140,3275 3460,3275 3540,3195 3540,3085 3585,3040 3895,3040 ; 3895,3040 4075,3040 ; 4075,3040 4473.84,3040 4540,3106.16 4540,3320 ; 4360,3930 4635,3930 4658.46,3906.54 C30.1 C31.1 4658.46,3703.46 4640,3685 4605,3685 4540,3620 4540,3320
  Bottom Layer w10: v2(3730,3665) 3725,3665 3755,3635 3755,3580 3795,3540 4002.5,3540 4127.5,3415 4335,3415 v1(4430,3320)
AVSS: C1.2 C2.2 C14.2 C15.2 C19.1 C28.2 C29.2 C30.2 C31.2 C32.2 C33.2 C35.2 C37.2 C40.2 C41.2 C42.2 C43.2 C44.2 R1.1 R21.1 R29.2 TP4.1 U1.13 U1.83 U3.1 U3.7 U3.15 U4.4 U5.4 U6.2 | length 3986.7
  Top Layer w10: C29.2 C28.2 ; v1@3130,3805 v1(3130.22,3804.78) ; U1.83 3433.72,4828.43 3685,4577.15 3685,4495 3660,4470 3515,4470 U1.13 3515,4315 v2(3485,4285) ; v4(3620,3560) 3660,3600 3660,3650 ; U3.1 3760,3500.94 3790,3470.94 v1(3790,3460) ; C41.2@3745,3101.54 C41.2@3748.46,3105 ; C19.1 4243.5,3968.5 v2(4245,3970)
  Bottom Layer w10: v1(2790,3515) v2(2895,3515) 2990,3420 v1(3050,3420) ; v2(3080,3855) v1(3130.22,3804.78) v1@3364.78,3804.78 ; v1@3355,3380 v1(3420,3445) ; v1(3365,3805) v2(3365,4000) ; v1(3480,3865) 3480,4280 v2(3485,4285) ; v4(3580.63,3560) v4(3620,3560) ; v4(3620,3512.76) v4(3620,3560) ; v4(3620,3607.24) v4(3620,3560) ; v1(3650,3135) 4165,3135 4225,3195 v2(4225,3215) ; v1(3790,3460) 3759.37,3460 v4(3659.37,3560) v4(3620,3560) ; v2(4245,3970) 4350,3865 v1(4480,3865)
  other v1: 3350,3360
D+: 1.3 J3.3 R4.1 | length 461.7
  Top Layer w10: J3.3 2305,5210 2389.44,5125.56 2485,5125.56 1.3 2567.2,5127.2 R4.1
D-: 1.2 J3.2 R3.1 | length 669.7
  Top Layer w10: J3.2 2258.74,5235 2305,5235 2400,5140 2475,5140 2530,5195 2530,5290 2542.24,5302.24 1.2 2567.2,5272.2 2605,5234.4 2605,5190 2630,5165 R3.1@2630,5130
DISCRETEOAOUTPUT: C25.2 C26.2 R38.2 U2.1 U3.14 U5.1 | length 2265.8
  Top Layer w10: U5.1 C26.2 ; v2(3175,3845) 3145,3875 3145,4000 3196.38,4051.38 C26.2 ; R38.2 3238.62,4255.16 C25.2 3238.62,4158.62 3196.38,4116.38 C26.2 ; v2(3282.13,3862.13) 3387.87,3862.13 3455,3795 3505,3795 3540,3830 v1(3555,3830) 3555,3867.32 3582.68,3895 3765,3895 3905,3755 U2.1 ; U3.14 3525.94,3500.94 3515,3490 3515,3475 3522.21,3467.79 3607.59,3467.79 v1(3617.79,3457.59)
  Bottom Layer w10: v2(3175,3845) 3265,3845 v2(3282.13,3862.13) ; v1(3555,3830) 3555,3805 3595,3765 3595,3705 3575,3685 3560,3685 3540,3665 3540,3505 3587.41,3457.59 v1(3617.79,3457.59)
DVCC: C3.1 C4.1 C5.1 C6.1 C8.1 C9.1 C36.1 C38.1 J1.1 R17.1 R18.1 R28.1 S8.1 TP1.1 U1.26 U1.64 U1.89 | length 8288.3
  Top Layer w10: C36.1 2245.32,3904.68 2265,3885 2265,3635 2243.43,3613.43 S8.1 ; C36.1@2180,3907.03 2180,3995 ; TP1.1 2180,3995 ; R28.1 2386.54,3875 ; v1(2475,3875) 2386.54,3875 ; v1(2820,4400) C9.1 C8.1 2950,4485 3025,4560 3025,4625 3110.31,4710.31 U1.89 ; v1@3430,5350 C6.1 C5.1 3495.31,5273.39 U1.64 ; U1.26 3938.78,4493.78 3965,4520 C4.1 C3.1 v2(3920,4425) ; v1(4240,4370) 4290,4370 ; R17.1@4290,4305 4290,4370 ; R18.1@4290,4530 4290,4370 ; 2180,3995 2305,3995 2386.54,3913.46 2386.54,3875
  Bottom Layer w10: v1(2475,3875) 2660,3875 2820,4035 v1(2820,4400) 2820,4495 2780,4535 2780,4610 2825,4655 2970,4655 3290,4975 3290,5275 3370,5355 v1(3425,5355) 3565,5355 3920,5000 3920,4760 3950,4730 3950,4670 3920,4640 v2(3920,4425) 3975,4370 v1(4240,4370) ; 3920,4965 4640,4965 4750,5075 4750,5860 4730,5880 J1.1
DVCC1: R2.2
EXTERNAL_FILTER_C1: C39.1 R36.2 U3.10 | length 921.1
  Top Layer w10: C39.1 3188.46,3426.54 3196.73,3418.27 ; R36.2 3205,3353.46 3205,3410 3196.73,3418.27 ; v1(3230,3445) 3203.27,3418.27 3196.73,3418.27 ; v1(3460,3715) 3460,3665 3480,3645 3480,3614.94 3515.26,3579.68 U3.10
  Bottom Layer w10: v1(3230,3445) 3355,3445 3380,3470 3380,3505 3307.55,3577.45 3307.55,3652.55 3350,3695 3400,3695 3420,3715 v1(3460,3715)
EXTERNAL_FILTER_C2: C39.2 R36.1 U3.9 | length 987.6
  Top Layer w10: C39.2 3205,3493.46 ; R36.1 3275,3356.54 3275,3465 3246.54,3493.46 3205,3493.46 ; U3.9 3517.91,3599.37 3495,3622.28 3495,3735 3470,3760 3425,3760 3385,3720 3235,3720 3180,3665 3180,3580 3201,3559 3201,3554.2 3205,3550.2 3205,3493.46
GAS_SUBCIRCUIT_OUTPUT: C27.2 R16.1 R39.1 R40.1 U4.1 | length 629.4
  Top Layer w10: C27.2 R16.1@4098.15,3808.62 ; R16.1 4118.46,3795 R40.1 ; R39.1@4206.54,3625 4206.54,3558.46 4250,3515 4340,3515 4360,3535 U4.1 ; R39.1 R40.1@4211.54,3785
GND: 1.1 BT1.2 C3.2 C4.2 C5.2 C6.2 C7.2 C8.2 C9.2 C10.2 C11.1 C12.1 C13.2 C16.1 C17.2 C18.2 C20.2 C21.2 C22.2 C23.2 C24.2 C34.2 C36.2 C38.2 D7.1 D8.1 J1.4 J2.10 J3.5 J12.2 J12.3 MH1.1 MH2.1 MH3.1 MH4.1 R6.1 R7.1 R12.1 R29.1 S2.2 S3.2 S4.2 S5.1 S6.2 S7.2 TP3.1 U1.27 U1.63 U1.90 | length 3004.9
  Top Layer w10: MH4.1@2055.3,6584.7 v3(2078.91,6584.7) v3(2251.09,6584.7) v3(2251.09,6485.3) v3(2078.91,6485.3) ; v3(2083.91,2630.3) v3(2256.09,2630.3) v3(2256.09,2729.7) v3(2083.91,2729.7) ; C20.2@2396.54,5300 2401.54,5295 C21.2 ; 1.1 2634.92,5359.92 v2(2635,5360) ; C17.2@2726.54,4715 C17.2@2731.54,4710 ; R7.1 2796.54,5348.46 v2(2790,5355) v2@2810,5355 ; v1(3430,5515) C6.2 C5.2 ; v2(3645,4130) 3645,4133.5 C11.1 ; v3(4728.91,2630.3) 4765.3,2630.3 v3(4815,2580.59) 4864.7,2630.3 v3(4901.09,2630.3) v3(4901.09,2729.7) 4864.7,2729.7 v3(4815,2779.41) 4778.61,2779.41 v3(4728.91,2729.7) ; v3(4785,6425.59) 4735.3,6475.3 v3(4698.91,6475.3) v3(4698.91,6574.7) 4735.3,6574.7 v3(4785,6624.41) 4834.7,6574.7 v3(4871.09,6574.7) v3(4871.09,6475.3)
  Bottom Layer w10: v3(2165,6435.59) MH4.1 ; MH3.1 2385,2680 v1(2390,2675) ; v1(2325,5665) v1(2325,5785) ; v2@2785,5360 v2(2790,5355) ; v1(3445,4745) v1(3515,4815)
  other v1: 3350,3120 2925,5385
  other v2: 3420,3200
  other v3: 2170,2580.59 2170,2779.41 2165,6634.41
JTAG_VCC_IN: J2.1 J11.1 | length 514.4
  Bottom Layer w10: J2.1 2685,4100 2740,4155 2740,4355 2700,4395 J11.1
JTAG_VCC_OUT: J2.3 J11.3 | length 111.2
  Top Layer w10: J2.3 2635,4200 2645,4190 2645,4200 J11.3
LCD_COM0_BACKPLANE: U1.30 U7.21 | length 2622.6
  Top Layer w10: U1.30 3932.52,4572.52 4155,4795 4410,4795 4440,4825 4440,5015 4540,5115 v1(4540,5180)
  Bottom Layer w10: U7.21 4315,6505 4490,6330 4490,5600 4540,5550 v1(4540,5180)
LCD_COM1_BACKPLANE: U1.31 U7.22 | length 2543.9
  Top Layer w10: U1.31 3932.2,4592.2 4150,4810 4340,4810 4409.23,4879.23 v1(4409.23,5180)
  Bottom Layer w10: U7.22 4215,6505 4465,6255 4465,5315 4409.23,5259.23 v1(4409.23,5180)
LCD_COM2_BACKPLANE: U1.32 U7.23 | length 2498.2
  Top Layer w10: U1.32 3931.89,4611.89 4145,4825 4305,4825 4355,4875 v1(4355,5140)
  Bottom Layer w10: U7.23 4115,6500 4365,6250 4365,5575 4345,5555 4345,5430 4315,5400 4315,5285 4355,5245 v1(4355,5140)
LCD_COM3_BACKPLANE: U1.33 U7.24 | length 2396.4
  Top Layer w10: U1.33 3931.57,4631.57 4140,4840 4245,4840 4295,4890 v1(4295,5115)
  Bottom Layer w10: U7.24 4015,6500 4267.68,6247.32 4267.68,5557.32 4295,5530 v1(4295,5115)
LCD_SEGMENT_OUTPUT_S0: U1.75 U7.1 | length 1209.8
  Top Layer w10: U7.1 2515,5515 2550,5480 2695,5480 2730,5445 3035,5445 3100,5380 3205,5380 3225,5360 3225,5180 3278.78,5126.22 U1.75
LCD_SEGMENT_OUTPUT_S1: U1.74 U7.2 | length 1138.5
  Top Layer w10: U7.2 2615,5530 2640,5505 2705,5505 2745,5465 3045,5465 3110,5400 3235,5400 3245,5390 3245,5190 3298.46,5136.54 U1.74
LCD_SEGMENT_OUTPUT_S2: U1.73 U7.3 | length 1073
  Top Layer w10: U7.3 2715,5525 2755,5485 3055,5485 3120,5420 3255,5420 3265,5410 3265,5200 3318.15,5146.85 U1.73
LCD_SEGMENT_OUTPUT_S3: U1.72 U7.4 | length 992.9
  Top Layer w10: U7.4 2815,5545 2855,5505 3065,5505 3130,5440 3275,5440 3285,5430 3285,5210 3337.83,5157.17 U1.72
LCD_SEGMENT_OUTPUT_S4: U1.71 U7.5 | length 921.5
  Top Layer w10: U7.5 2915,5550 2940,5525 3075,5525 3140,5460 3295,5460 3305,5450 3305,5220 3357.52,5167.48 U1.71
LCD_SEGMENT_OUTPUT_S5: U1.70 U7.6 | length 844.3
  Top Layer w10: U7.6 3015,5565 3035,5545 3085,5545 3150,5480 3315,5480 3325,5470 3325,5230 3377.2,5177.8 U1.70
LCD_SEGMENT_OUTPUT_S6: U1.69 U7.7 | length 787.6
  Top Layer w10: U7.7 3115,5545 3160,5500 3335,5500 3345,5490 3345,5240 3396.89,5188.11 U1.69
LCD_SEGMENT_OUTPUT_S7: U1.68 U7.8 | length 710.4
  Top Layer w10: U7.8 3215,5550 3245,5520 3345,5520 3365,5500 3365,5250 3416.57,5198.43 U1.68
LCD_SEGMENT_OUTPUT_S8: U1.67 U7.9 | length 618.6
  Top Layer w10: U7.9 3315,5580 3385,5510 3385,5251.96 3436.26,5200.7 U1.67
LCD_SEGMENT_OUTPUT_S9: U1.62 U7.10 | length 651.3
  Top Layer w10: U7.10 3575,5442.5 3575,5265 3534.68,5224.69 U1.62
LCD_SEGMENT_OUTPUT_S10: U1.61 U7.11 | length 618.3
  Top Layer w10: U7.11 3595,5522.5 3595,5260 3554.37,5219.37 U1.61
LCD_SEGMENT_OUTPUT_S11: U1.60 U7.12 | length 585.3
  Top Layer w10: U1.60 3574.06,5209.06 3615,5250 U7.12
LCD_SEGMENT_OUTPUT_S12: U1.59 U7.13 | length 618.6
  Top Layer w10: U1.59 3593.74,5198.74 3635,5240 3635,5460 3715,5540 U7.13
LCD_SEGMENT_OUTPUT_S13: U1.58 U7.14 | length 684.1
  Top Layer w10: U1.58 3613.43,5188.43 3655,5230 3655,5435 3685,5465 3740,5465 3815,5540 U7.14
LCD_SEGMENT_OUTPUT_S14: U1.57 U7.15 | length 758.4
  Top Layer w10: U1.57 3633.11,5178.11 3675,5220 3675,5425 3695,5445 3820,5445 3915,5540 U7.15
LCD_SEGMENT_OUTPUT_S15: U1.56 U7.16 | length 823.8
  Top Layer w10: U1.56 3652.8,5167.8 3695,5210 3695,5405 3715,5425 3895,5425 4015,5545 U7.16
LCD_SEGMENT_OUTPUT_S16: U1.55 U7.17 | length 892.3
  Top Layer w10: U1.55 3672.48,5157.48 3715,5200 3715,5385 3735,5405 3975,5405 4115,5545 U7.17
LCD_SEGMENT_OUTPUT_S17: U1.54 U7.18 | length 963.6
  Top Layer w10: U1.54 3692.17,5147.17 3735,5190 3735,5370 3750,5385 4055,5385 4215,5545 U7.18
LCD_SEGMENT_OUTPUT_S18: U1.53 U7.19 | length 1034.9
  Top Layer w10: U1.53 3711.85,5136.85 3755,5180 3755,5355 3765,5365 4135,5365 4315,5545 U7.19
LCD_SEGMENT_OUTPUT_S19: U1.52 U7.20 | length 1097.5
  Top Layer w10: U1.52 3731.54,5126.54 3775,5170 3775,5330 3790,5345 4210,5345 4415,5550 U7.20
LCD_SEGMENT_OUTPUT_S20: U1.51 U7.38 | length 2182.2
  Top Layer w10: U1.51 3751.22,5126.22 v1(3827.5,5202.5)
  Bottom Layer w10: U7.38 2615,6515 3370,5760 3490,5760 3565,5685 3565,5550 3827.5,5287.5 v1(3827.5,5202.5) v1@3810,5185
LCD_SEGMENT_OUTPUT_S21: U1.50 U7.37 | length 2371.5
  Top Layer w10: U1.50 3886.22,4966.22 4005,5085 4005,5140 3985,5160 3935,5160 v1(3895,5200)
  Bottom Layer w10: U7.37 2715,6515 3445,5785 3565,5785 3665,5685 3665,5535 3895,5305 v1(3895,5200)
LCD_SEGMENT_OUTPUT_S22: U1.49 U7.36 | length 2380.6
  Top Layer w10: U1.49 3896.54,4946.54 4035,5085 4035,5175 4010,5200 v1(3960,5200)
  Bottom Layer w10: U7.36 2815,6515 3525,5805 3645,5805 3765,5685 3765,5525 3960,5330 v1(3960,5200)
LCD_SEGMENT_OUTPUT_S23: U1.48 U7.35 | length 2372.2
  Top Layer w10: U1.48 3906.85,4926.85 4065,5085 4065,5205 4010,5260 v1(4010,5265)
  Bottom Layer w10: U7.35 2915,6500 3585,5830 3725,5830 3875,5680 3875,5480 4010,5345 v1(4010,5265)
LCD_SEGMENT_OUTPUT_S24: U1.47 U7.34 | length 2369
  Top Layer w10: U1.47 3912.17,4907.17 4080,5075 4080,5215 4060,5235 v1(4060,5305)
  Bottom Layer w10: U7.34 3015,6500 3660,5855 3805,5855 3965,5695 3965,5480 4060,5385 v1(4060,5305)
LCD_SEGMENT_OUTPUT_S25: U1.46 U7.33 | length 2399.8
  Top Layer w10: U1.46 3917.48,4887.48 4070,5040 4085,5040 4100,5055 4100,5210 4115,5225 v1(4115,5265)
  Bottom Layer w10: U7.33 3115,6485 3720,5880 3885,5880 4065,5700 4065,5520 4115,5470 v1(4115,5265)
LCD_SEGMENT_OUTPUT_S26: U1.45 U7.32 | length 2464.9
  Top Layer w10: U1.45 3927.8,4867.8 4085,5025 4105,5025 4120,5040 4120,5200 4170,5250 v1(4170,5305)
  Bottom Layer w10: U7.32 3215,6480 3790,5905 4010,5905 4170,5745 v1(4170,5305)
LCDCAP_R33: C24.1 R9.2 U1.29 | length 1006.4
  Top Layer w10: U1.29 3932.83,4552.83 4100,4720 C24.1 4214.8,4629.8 4195,4610 4195,4355 4183.5,4343.5 R9.2
LED7: R35.1 U1.35 | length 1687.5
  Top Layer w10: U1.35 3925.94,4670.94 4130,4875 4210,4875 4225,4890 4225,5160 4300,5235 4690,5235 4750,5175 R35.1
LED8: R34.1 U1.34 | length 1590.3
  Top Layer w10: U1.34 3931.26,4651.26 4140,4860 4225,4860 4240,4875 4240,5155 4305,5220 4585,5220 4615,5190 4615,5120 4550,5055 R34.1
LMP_VREF: C42.1 R37.2 U3.11 | length 1773.7
  Top Layer w10: U3.11 3510.43,3560 3465,3605.43 3465,3635 3400,3700 3245,3700 3215,3670 3215,3560 3535,3240 3685,3240 3760,3315 3830,3315 3900,3385 3990,3385 4030,3345 4030,3255 4021.54,3246.54 R37.2 C42.1
MSP4_PX_X_LMP_MENB: U1.38 U3.2 | length 2208.2
  Top Layer w10: U3.2 3844.37,3520.63 v1(3870,3495) ; U1.38 3875,4730 v1(3900,4705)
  Bottom Layer w10: v1(3870,3495) 3810,3495 3660,3645 3660,3735 3595,3800 3595,3927.82 3652.18,3985 3652.18,4027.18 3695,4070 3695,4255 3475,4475 3475,4645 3595,4765 3735,4765 3795,4705 v1(3900,4705)
MSP_CPCAP: C19.2 U1.17 | length 815.5
  Top Layer w10: U1.17 3593.74,4386.26 3605,4375 3660,4375 3810,4225 3875,4225 3930,4170 3930,4080 3953.69,4056.31 4083.69,4056.31 4108.5,4031.5 C19.2
MSP_PORT_P1.5: S7.1 U1.39 | length 3009.3
  Top Layer w10: U1.39 3959.68,4749.69 4115,4905 4165,4905 4210,4950 4210,5165 4295,5250 4855,5250 4885,5220 4885,3905 4835,3855 ; S7.1@4833.58,3641.5 4833.58,3853.58
MSP_PORT_P1.6: S4.1 U1.40 | length 6740.3
  Top Layer w10: S4.1 2323.58,2926.42 2245,3005 2245,3115 2420,3290 3095,3290 3125,3260 3450,3260 3525,3185 3525,3060 3560,3025 4750,3025 4900,3175 4900,5225 4860,5265 4290,5265 4195,5170 4195,4955 4165,4925 4110,4925 3954.37,4769.37 U1.40
MSP_PORT_P1.7: S5.2 U1.41 | length 6320.5
  Top Layer w10: S5.2 2473.5,2988.1 2615,3129.6 2615,3170 2715,3270 3075,3270 3175,3170 3215,3170 3310,3075 3475,3075 3540,3010 4755,3010 4915,3170 4915,5230 4865,5280 4285,5280 4180,5175 4180,4965 4160,4945 4105,4945 3949.06,4789.06 U1.41
MSP_PORT_P3.0: S3.1 U1.42 | length 5861.8
  Top Layer w10: S3.1 2893.58,3206.42 2915,3185 2915,3120 2960,3075 3060,3075 3080,3055 3470,3055 3530,2995 4760,2995 4930,3165 4930,5235 4870,5295 4280,5295 4165,5180 4165,4975 4155,4965 4100,4965 3943.74,4808.74 U1.42
MSP_PORT_P3.1: S2.1 U1.43 | length 6308.3
  Top Layer w10: S2.1 2598.58,2833.58 2655,2890 2655,2935 2715,2995 3385,2995 3435,2945 4730,2945 4945,3160 4945,5240 4765,5420 4385,5420 4150,5185 4150,5000 4135,4985 4095,4985 3938.43,4828.43 U1.43
MSP_PORT_P3.2: S6.1 U1.44 | length 5547.1
  Top Layer w10: S6.1@3171.5,2926.42 4731.42,2926.42 4960,3155 4960,5265 4790,5435 4380,5435 4135,5190 4135,5020 4117.5,5002.5 4087.5,5002.5 3933.11,4848.11 U1.44
MSP_PORT_P6.0_A0: R40.2 U1.97 U3.8 | length 2340.6
  Top Layer w10: U1.97 3307.83,4552.83 3355,4600 v1@3582.18,4600 ; U3.8 3520,3619.06 3510,3629.06 3510,3670 3532.13,3692.13 3597.13,3692.13 v1(3740,3835) ; v1(3582.18,4525) v1(3582.18,4598.51) ; v1(3945,3980) 3980,3980 4065,3895 4220,3895 4268.46,3846.54 R40.2
  Bottom Layer w10: v1(3582.18,4525) 3582.18,4507.82 3740,4350 v1(3740,3835) 3820,3835 3855,3870 3855,3950 3885,3980 v1(3945,3980)
MSP_RST: C18.1 J2.12 R2.1 U1.96 | length 993.2
  Top Layer w10: J2.12 2455,4605 2500,4650 2625,4650 2645,4630 2645,4580 2675,4550 2820,4550 v1(2855,4585) ; 2791.5,4550 R2.1 C18.1@2791.5,4658.83 ; v1(3135,4555) 3152.52,4572.52 U1.96
  Bottom Layer w10: v1(2855,4585) 2885,4555 v1(3135,4555)
MSP_TCK: J2.8 U1.95 | length 1781.3
  Top Layer w10: J2.8 2355,4300 2355,4035 2420,3970 2750,3970 2790,4010 2790,4265 2805,4280 2950,4280 3010,4340 3010,4420 3100,4510 3100,4575 3117.2,4592.2 U1.95
MSP_TDI: J2.4 U1.93 | length 1554.7
  Top Layer w10: J2.4 2405,4200 2384,4179 2384,4045.8 2429.8,4000 2730,4000 2760,4030 2760,4285 2785,4310 2930,4310 2970,4350 2970,4430 3070,4530 3070,4595 3106.57,4631.57 U1.93
MSP_TDO: J2.2 U1.92 | length 1327
  Top Layer w10: J2.2 2455,4035 2475,4015 2720,4015 2745,4040 2745,4295 2775,4325 2920,4325 2950,4355 2950,4435 3055,4540 3055,4605 3101.26,4651.26 U1.92
MSP_TEST/VPP: J2.7 U1.91 | length 898.6
  Top Layer w10: J2.7 2610,4345 2915,4345 2930,4360 2930,4440 3040,4550 3040,4615 3095.94,4670.94 U1.91
MSP_TMS: J2.6 U1.94 | length 1652.8
  Top Layer w10: J2.6 2370,4215 2370,4040 2425,3985 2740,3985 2775,4020 2775,4275 2795,4295 2940,4295 2990,4345 2990,4425 3085,4520 3085,4585 3111.89,4611.89 U1.94
MSP_UCB1SCL_SCL_LMP_SCL: R17.2 U1.66 U3.3 | length 2463.3
  Top Layer w10: U1.66 3455.94,4934.06 v1(3690,4700) ; U3.3 3695.12,3540 3960,3540 4005,3585 v1(4005,3645) ; v2(4285,4145) 4295,4155 R17.2
  Bottom Layer w10: v1(3690,4700) 3735,4700 3772.5,4662.5 3772.5,4462.5 3875,4360 3940,4360 4172.5,4127.5 ; v1(4005,3645) 4100,3645 4145,3690 4145,4100 4190,4145 v2(4285,4145)
MSP_UCB1SDA_SDA_LMP_SDA: R18.2 U1.65 U3.4 | length 2766.9
  Top Layer w10: U1.65 3475.63,4974.37 3725,4725 v1(3725,4620) ; U3.4 3740,3560 3775,3595 3775,3675 3805,3705 v1(3845,3705) ; v2(4095,4150) v2(4155,4210) ; v2(4240,4460) 4230,4470 4230,4590 4250,4610 R18.2@4290,4610
  Bottom Layer w10: v1(3725,4620) 3725,4470 4070,4125 ; v1(3845,3705) 4095,3705 4130,3740 4130,4065 4070,4125 ; v2(4095,4150) 4070,4125 ; v2(4155,4210) 4285,4340 4285,4415 v2(4240,4460)
MSP_VBAK: C16.2 U1.86 | length 698.7
  Top Layer w10: C16.2 2689.68,4519.1 2705.58,4535 2975,4535 3010,4570 3010,4655 3124.37,4769.37 U1.86
NetBT1_1: BT1.1 BT2.2 | length 2100.5
  Bottom Layer w10: BT2.2 3086.02,5425 3540,5425 3940,5025 4525,5025 4660,5160 BT1.1
NetC26_1: C26.1 R13.1 R14.2 | length 350.8
  Top Layer w10: C26.1 3243.62,4048.62 3191.54,3996.54 R13.1 3191.54,3879.05 3261.21,3809.37 R14.2
NetC41_1: C41.1 U6.1 | length 131.5
  Top Layer w10: C41.1@3745,3168.46 3745,3225 3762.4,3242.4 U6.1
NetD1_2: D1.2 J3.1 | length 194.9
  Top Layer w10: J3.1 2311.18,5261.18 2330.53,5280.53 D1.2
NetD3_1: D3.1 J5.2 | length 221.7
  Top Layer w10: J5.2 2280,5445 2305.8,5470.8 2305.8,5554.2 2290,5570 D3.1@2260.53,5570
NetD7_2: D7.2 R26.2 | length 239
  Top Layer w10: D7.2 R26.2
NetD8_2: D8.2 R27.2 | length 244
  Top Layer w10: D8.2 4760,4199.53 R27.2
NetJ3_6: J3.6 J3.7 J3.8 J3.9 J3.10 J3.11 R6.2 | length 637.5
  Top Layer w10: R6.2 2229.06,4995 J3.9 ; J3.10 2246.57,5111.57 2207.2,5072.2 J3.9 ; J3.11 2191.22,5308.43 J3.6 J3.7 J3.8 J3.9
NetQ1_1: Q1.1 R15.1 | length 180.2
  Top Layer w10: R15.1@4101.5,3400 4112.4,3410.91 Q1.1
NetR1_2: R1.2 U1.12 | length 418.5
  Top Layer w10: R1.2 3491.5,4083.5 3474.85,4100.15 3454.85,4100.15 3450,4105 3450,4310 3495.31,4355.31 U1.12
NetR8_2: R8.2 S1.1 S1.3 | length 627.3
  Top Layer w10: S1.3 S1.1 2443.5,4846.5 2495,4795 R8.2
NetR26_1: R26.1 R34.2 | length 257.6
  Top Layer w10: R34.2 4550,4634.53 4560,4624.53 R26.1
NetR27_1: R27.1 R35.2 | length 257.6
  Top Layer w10: R35.2 4750,4635 4760,4625 R27.1
NetR37_1: R37.1 U6.5 | length 129.3
  Top Layer w10: U6.5 3907.24,3297.24 3923.46,3313.46 R37.1@3975,3313.46
OPAMP0_INVERTINGINPUT: C25.1 R13.2 U1.2 U5.2 | length 909.5
  Top Layer w10: U5.2 3155,4120 3191.38,4156.38 C25.1 ; v2@3146.38,4165 v2(3140,4165) 3170,4135 ; v2(3250,4120) 3291.81,4120 ; R13.2 3258.46,3993.46 3291.81,4026.81 3291.81,4120 ; U1.2 3298.46,4361.65 3291.81,4355 3291.81,4120
  Bottom Layer w10: v2(3140,4165) 3185,4120 v2(3250,4120)
OPAMP0_OUTPUT/COU_ELE: R38.1 U1.1 | length 230.4
  Top Layer w10: R38.1 3181.54,4316.54 3198.46,4333.46 3215,4333.46 3248.46,4333.46 3278.78,4363.78 U1.1
OPAMP1_INVERTINGINPUT: C27.1 R16.2 R19.2 U1.6 U4.2 | length 1958.3
  Top Layer w10: v2(3377.2,4352.2) U1.6 ; v1(3420,3945) 3435,3930 3813.46,3930 3835,3908.46 R19.2@3935,3908.46 ; R19.2 4001.54,3903.46 4020,3885 4020,3865 3990,3835 3990,3770 3998.62,3761.38 C27.1 4085.16,3761.38 R16.2 4101.5,3693.5 4140,3655 4140,3540 4190,3490 4390,3490 4410,3510 U4.2
  Bottom Layer w10: v2(3377.2,4352.2) 3377.2,4247.8 3420,4205 v1(3420,3945)
OPAMP1_OUTPUT/A0: R39.2 U1.5 | length 1708
  Top Layer w10: U1.5 3357.52,4482.52 3435,4560 v1(3530,4560) ; v2(4065,3990) 4065,3945 4100,3910 4310,3910 4330,3890 4330,3745 4278.46,3693.46 R39.2
  Bottom Layer w10: v1(3530,4560) 3600,4560 4065,4095 v2(4065,3990)
P5.0: C14.1 C15.1 U1.9 | length 322.2
  Top Layer w10: C14.1 3406.93,4266.93 ; C15.1 3410,4325 3436.26,4351.26 U1.9
PU.0/DP: C23.1 R4.2 R5.1 R7.2 U1.77 | length 3298.5
  Top Layer w10: R4.2 2565,4963.46 2563.46,4965 2383.46,4965 2338.46,4920 2125,4920 2060,4985 2060,5605 2170,5715 2400,5715 2450,5665 2450,5595 2492.5,5552.5 2492.5,5502.5 2570,5425 2861.93,5425 ; R5.1 R7.2 2863.46,5425 3025,5425 3115,5335 3115,5080 3145,5050 3145,4965 3163.46,4946.54 U1.77
PU.1/DM: C22.1 R3.2 U1.79 | length 1013.2
  Top Layer w10: R3.2@2640,5045 2640,4968.46 C22.1 2650,4965 2710,5025 v2(2750,5025) ; v1(3095,4950) 3095,4920 3107.83,4907.17 U1.79
  Bottom Layer w10: v2(2750,5025) 2750,5035 2870,5155 3090,5155 3135,5110 3135,4995 3095,4955 v1(3095,4950)
PUR: R5.2 R8.1 U1.78 | length 1219.5
  Top Layer w10: R8.1 2725,4795 v2(2770,4840) ; R5.2 3085,5270 3095,5260 v1(3095,5020) 3130,4985 3130,4955 3158.15,4926.85 U1.78
  Bottom Layer w10: v2(2770,4840) 2770,4970 2925,5125 3065,5125 3095,5095 v1(3095,5020)
R03: R11.1 R12.2 U1.22 | length 575.2
  Top Layer w10: U1.22 3692.17,4377.83 3765,4305 3895,4305 3905,4295 3905,4217.15 3937.15,4185 R11.1 3970,4160 3980,4150 4020,4150 4031.5,4138.5 R12.2
R13: R10.1 R11.2 U1.24 | length 532.6
  Top Layer w10: U1.24 3731.54,4378.46 3785,4325 3905,4325 3925,4305 3925,4235 3935,4225 4032.99,4225 ; R10.1 4032.99,4262.01 4032.99,4225 ; R11.2 4032.99,4225
R23: R9.1 R10.2 U1.25 | length 356.1
  Top Layer w10: U1.25 3751.22,4383.78 3791.5,4343.5 R9.1 R10.2
REF_ELE: Q1.3 R14.1 U2.2 U3.13 | length 1415.4
  Top Layer w10: v1(3115,3690) 3115,3730 3154.65,3769.65 R14.1 ; v2(3270,3645) 3305,3610 U2.2 3385,3535 3440,3480 ; U3.13 3515.63,3520.63 3475,3480 3440,3480 ; v1(3730,3400) 3715,3415 3595,3415 3565,3445 3475,3445 3440,3480 ; v2(4010,3480) 4011.22,3481.22 Q1.3
  Bottom Layer w10: v1(3115,3690) 3160,3645 v2(3270,3645) ; v1(3730,3400) 3890,3400 3970,3480 v2(4010,3480)
V18: C7.1 U1.82 | length 570.6
  Top Layer w10: v1(3015,4865) 3031.89,4848.11 U1.82 ; v1(3185,5040) C7.1@3185,5115.44
  Bottom Layer w10: v1(3015,4865) 3015,4890 3030,4905 3110,4905 3145,4940 3145,4970 3185,5010 v1(3185,5040)
VBAT: J1.2 U1.87 | length 2340.2
  Top Layer w10: U1.87 3259.68,4749.69 v1(3300,4790) ; v1(3810,5025) 3810,5060 3805,5065 3830,5090 v1(3940,5090)
  Bottom Layer w10: v1(3300,4790) 3535,5025 v1(3810,5025) ; v1(3940,5090) 3942.13,5087.87 4202.13,5087.87 4235,5055 4500,5055 4600,5155 4600,5225 4575,5250 4575,5760 4595,5780 J1.2
VBUS: 1.4 C20.1 C21.1 D1.1 U1.80 | length 1791.7
  Top Layer w10: D1.1 2459.47,5304 2463.46,5300 2463.46,5215 C21.1 2505,5210 2515,5220 2515,5345 2580,5410 2695,5410 2730,5375 2730,5225 2712.76,5207.76 1.4 2642.8,5177.2 2660,5160 2760,5160 2820,5220 3025,5220 3060,5185 3060,4915 3087.52,4887.48 U1.80
VCC_VUSB: BT2.1 J5.1 J11.2 J12.1 S8.2 | length 3882.3
  Bottom Layer w10: J5.1 2075,5445 2050,5420 2050,4375 2090,4335 2090,4250 ; S8.2 2090,3515 ; J11.2 2605,4250 2090,4250 ; BT2.1 2175.91,3204.09 J12.1 2090,3515 ; 2090,3515 2090,4250
VCM: C43.1 C44.1 R20.1 R21.2 U1.99 U1.100 U4.3 U5.3 | length 4636
  Top Layer w10: v1@2940,4210 v1(2935,4210) 2935,4240 3038.46,4343.46 C43.1@3060,4343.46 ; R20.1 2985,3630 ; R21.2 2985,3630 ; C43.1 C43.1@3060,4343.46 ; U1.100 3143.78,4493.78 3130,4480 3130,4205 3095,4170 U5.3 2977.41,4170 2955,4147.59 2955,4075 2970,4060 3015,4060 3035,4040 3065,4040 3075,4030 C44.1 3116.54,3998.46 3124.8,3990.2 3124.8,3849.8 3055,3780 v1(3055,3630) 2985,3630 ; U1.99 3133.46,4513.46 3110,4490 3110,4425 3075,4425 3060,4410 C43.1@3060,4343.46 ; v2(4295,3235) 4295,3410 4315,3430 4425,3430 4460,3465 U4.3
  Bottom Layer w10: v1(2935,4210) 2935,3945 3055,3825 v1(3055,3630) 3055,3495 3470,3080 4140,3080 v2(4295,3235)
VCORE: C10.1 U1.28 | length 266.2
  Top Layer w10: U1.28 3820.98,4535 3940,4535 4015,4610 C10.1
VUSB: C34.1 D3.2 S1.2 S1.4 U1.81 | length 3078.3
  Top Layer w10: S1.4 S1.2 2176.5,4846.5 2230,4900 v2(2450,4900) ; v1(2170,5640) 2265,5640 2325,5580 2379.47,5580 2389.47,5570 2415,5570 2430,5555 2430,5491.54 C34.1 ; v2(2740,5095) 2845,5200 2995,5200 3025,5170 3025,4915 3072.2,4867.8 U1.81
  Bottom Layer w10: v1(2170,5640) 2225,5640 2450,5415 2450,4940 ; v2(2450,4900) 2450,4940 ; v2(2740,5095) 2605,5095 2450,4940
WOR_ELE: Q1.2 R19.1 U2.3 U3.12 | length 1225
  Top Layer w10: v1(3450,3525) 3484.68,3525 3500,3540.32 U3.12 ; v1(3530,3410) 3530,3375 3555,3350 U2.3@3595,3350 ; U2.3 3740,3345 3800,3405 3845,3405 3975,3535 4025,3535 4037.6,3547.6 Q1.2 4037.6,3607.6 4060,3630 4060,3660 3940,3780 R19.1 ; R19.1@3945,3836.54 R19.1@3945,3856.54
  Bottom Layer w10: v1(3450,3525) 3450,3480 3475,3455 3475,3430 3495,3410 v1(3530,3410)
XIN: C11.2 U1.15 Y1.1 | length 351.6
  Top Layer w10: U1.15 3554.37,4365.63 3580,4340 3610,4340 3646.18,4303.82 Y1.1 3646.18,4208.82 3658.5,4196.5 C11.2@3720,4196.5
XOUT: C12.2 U1.14 Y1.2 | length 284.8
  Top Layer w10: C12.2@3475,4206.5 3531.5,4206.5 3543.82,4218.82 Y1.2 3543.82,4326.18 3535,4335 3535,4425.55 U1.14
XT2IN: C13.1 U1.84 Y2.2 | length 765.1
  Top Layer w10: C13.1@2813.46,4955 2865,4955 2870,4960 2870,5072.01 2885,5087.01 Y2.2@2950,5087.01 ; Y2.2@2950,5095 2950,4875 3016.26,4808.74 U1.84
XT2OUT: C17.1 U1.85 Y2.1 | length 445.1
  Top Layer w10: C17.1@2798.46,4710 2801.46,4712.99 2950,4712.99 3032.99,4712.99 3109.06,4789.06 U1.85
pads on no net: BT1.MH1 BT2.MH1 J1.3 J2.5 J2.9 J2.11 J2.13 J2.14 J3.4 Logo1.0 S2.3 S2.4 S3.3 S3.4 S4.3 S4.4 S5.3 S5.4 S6.3 S6.4 S7.3 S7.4 S8.3 U1.3 U1.4 U1.7 U1.8 U1.10 U1.11 U1.18 U1.19 U1.20 U1.21 U1.23 U1.36 U1.37 U1.76 U1.88 U1.98 U2.7 U2.8 U2.9 U3.5 U4.5 U4.6 U4.7 U5.5 U5.6 U5.7 U7.25 U7.26 U7.27 U7.28 U7.29 U7.30 U7.31 Y1.3

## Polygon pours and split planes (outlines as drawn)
GND on Top Layer "Bottom Layer-No Net" (solid, pour order 45): 2310,6695 2310,6365 2100,6365 2005,6365 2005,6335 2005,2840 2310,2840 2335,2840 2335,2505 4660,2505 4660,2840 4980,2840 4980,6365 4635,6365 4635,6475 4635,6695
GND on Top Layer "Bottom Layer-No Net" (solid, pour order 46): 2000,6705 4980,6705 4980,4595 4980,3540 4980,2750.02 4980,2615 4980,2550 4980,2515 4980,2485 4980,2475 2000,2475
AVSS on Top Layer "AVSS_L01_P044" (solid, remove dead copper, pour order 44): 2420,3425 2850,3425 2915,3362.71 2915,3285 3459.44,3285.56 3520,3225 3520,3050 4565,3050 4565,3680 4860,3680 4860,3925 4315,3930 4315,4050 3460,4050 3460,4220 3543.82,4220 3543.82,4523.56 3545,4535 3420.19,4530.77 3100,4530 2795,4225 2795,3845 2420,3845 2420,3425
GND on Bottom Layer "Bottom Layer-No Net" (solid, pour order 47): 2000,6705 2310,6705 4980,6705 4980,6365 4980,2840 4980,2475 2000,2475 2000,2840

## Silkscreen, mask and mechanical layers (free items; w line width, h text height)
Mechanical 1:
  lines w47.24: 2000,2475 4980,2475 4980,6705 2000,6705 2000,2475

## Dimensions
2000,6705 to 4980,6705 on Mechanical 2
4980,6705 to 2000,6705 on Mechanical 2
2000,2480 to 2000,6705 on Mechanical 2
2000,6705 to 2000,2475 on Mechanical 2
